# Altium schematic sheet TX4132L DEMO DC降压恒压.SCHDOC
size B; SheetNumber: 0; SheetTotal: 0
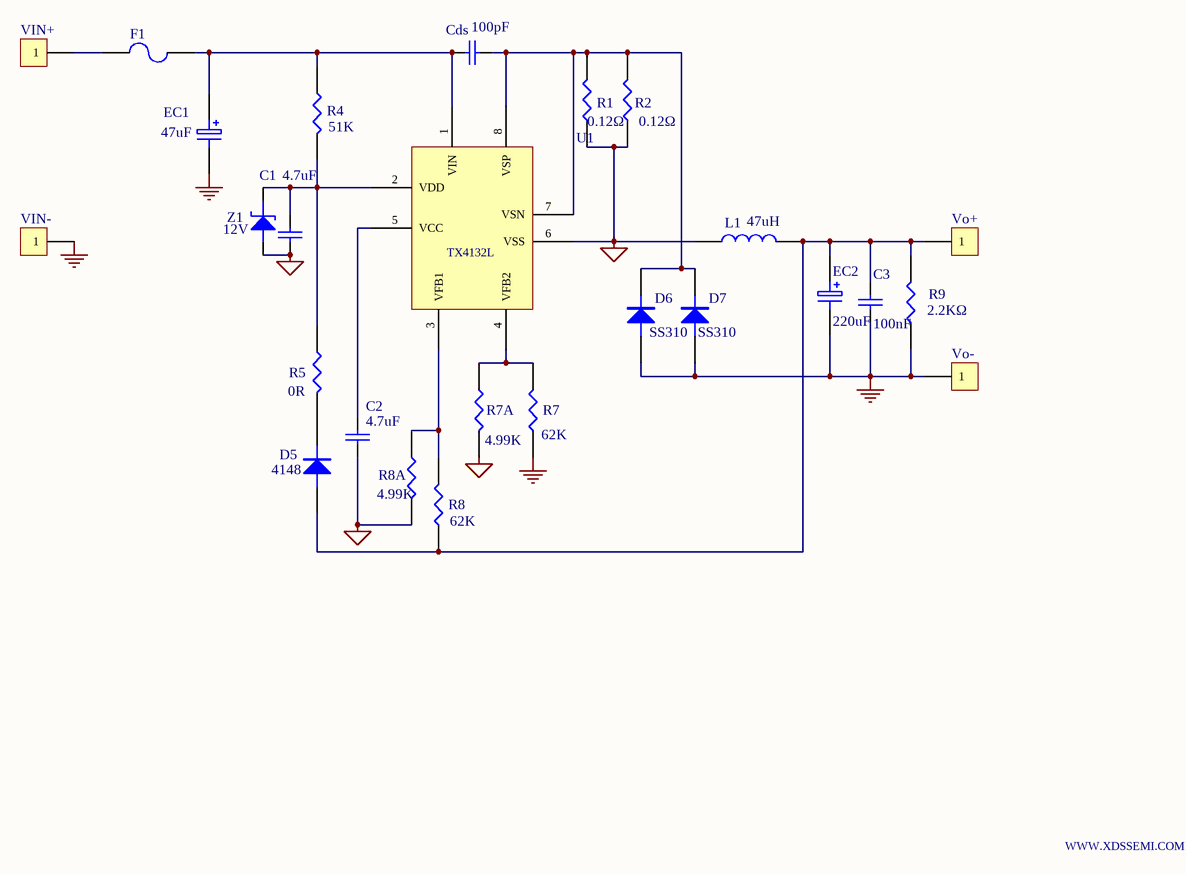
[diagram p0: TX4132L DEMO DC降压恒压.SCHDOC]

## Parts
C1  (no value)  [R0805]
C2  (no value)  [R1206]
C3  (no value)  [R1206]
Cds  (no value)
D5  (no value)
D6  (no value)  [SMB]
D7  (no value)  [SMB]
EC1  (no value)  [c10*16]
EC2  (no value)  [C10*16]
F1  (no value)
L1  (no value)  [L12*12]
R1  (no value)  [R1206]
R2  (no value)  [R1206]
R4  (no value)  [R1206]
R5  (no value)  [R1206]
R7  (no value)  [r0805]
R7A  (no value)  [r0805]
R8  (no value)  [r0805]
R8A  (no value)  [r0805]
R9  (no value)  [R0805]
U1  TX4132L
VIN+  (no value)  [pad]
VIN-  (no value)
Vo+  (no value)  [pad]
Vo-  (no value)  [pad]
Z1  (no value)

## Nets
GND: C3.2 D6.1(A) D7.1(A) EC1.2 EC2.2 R7.1 R9.1 VIN-.1 Vo-.1
SGND: C1.2 C2.2 L1.1 R1.1 R2.1 R7A.2 R8A.2 U1.6(VSS) Z1.1(A)
NetC1_1: C1.1 R4.2 R5.1 U1.2(VDD) Z1.2(K)
NetC2_1: C2.1 U1.5(VCC)
NetC3_1: C3.1 D5.1(A) EC2.1 L1.2 R8.1 R9.2 Vo+.1
NetCds_1: Cds.1 EC1.1 F1.1 R4.1 U1.1(VIN)
NetCds_2: Cds.2 D6.2(K) D7.2(K) R1.2 R2.2 U1.7(VSN) U1.8(VSP)
NetD5_2: D5.2(K) R5.2
NetF1_2: F1.2 VIN+.1
NetR7_2: R7.2 R7A.1 U1.4(VFB2)
NetR8_2: R8.2 R8A.1 U1.3(VFB1)

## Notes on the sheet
- (near Cds) 100pF
- (near EC1) 47uF
- 4.7uF
- (near R4) 51K
- 0.12Ω
- (near R2) 0.12Ω
- (near Z1) 12V
- (near L1) 47uH
- (near R9) 2.2KΩ
- SS310
- (near D7) SS310
- 220uF
- (near R9) 100nF
- (near R5) 0R
- (near C2) 4.7uF
- 4.99K
- (near R7) 62K
- (near D5) 4148
- (near R8A) 4.99K
- (near R8) 62K
- WWW.XDSSEMI.COM

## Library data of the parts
C1-C3 Cds = CAP: Capacitor
D5-D7 = DIODE
EC1 EC2 = ELECTRO1: Electrolytic Capacitor
F1 = FUSE2: Fuse
L1 = INDUCTOR
R1 R2 R4 R5 R7 R7A R8 R8A R9 = RES1
U1 = TX413X
VIN+ VIN- Vo+ Vo- = CON1: Connector
Z1 = ZENER2: Zener Diode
